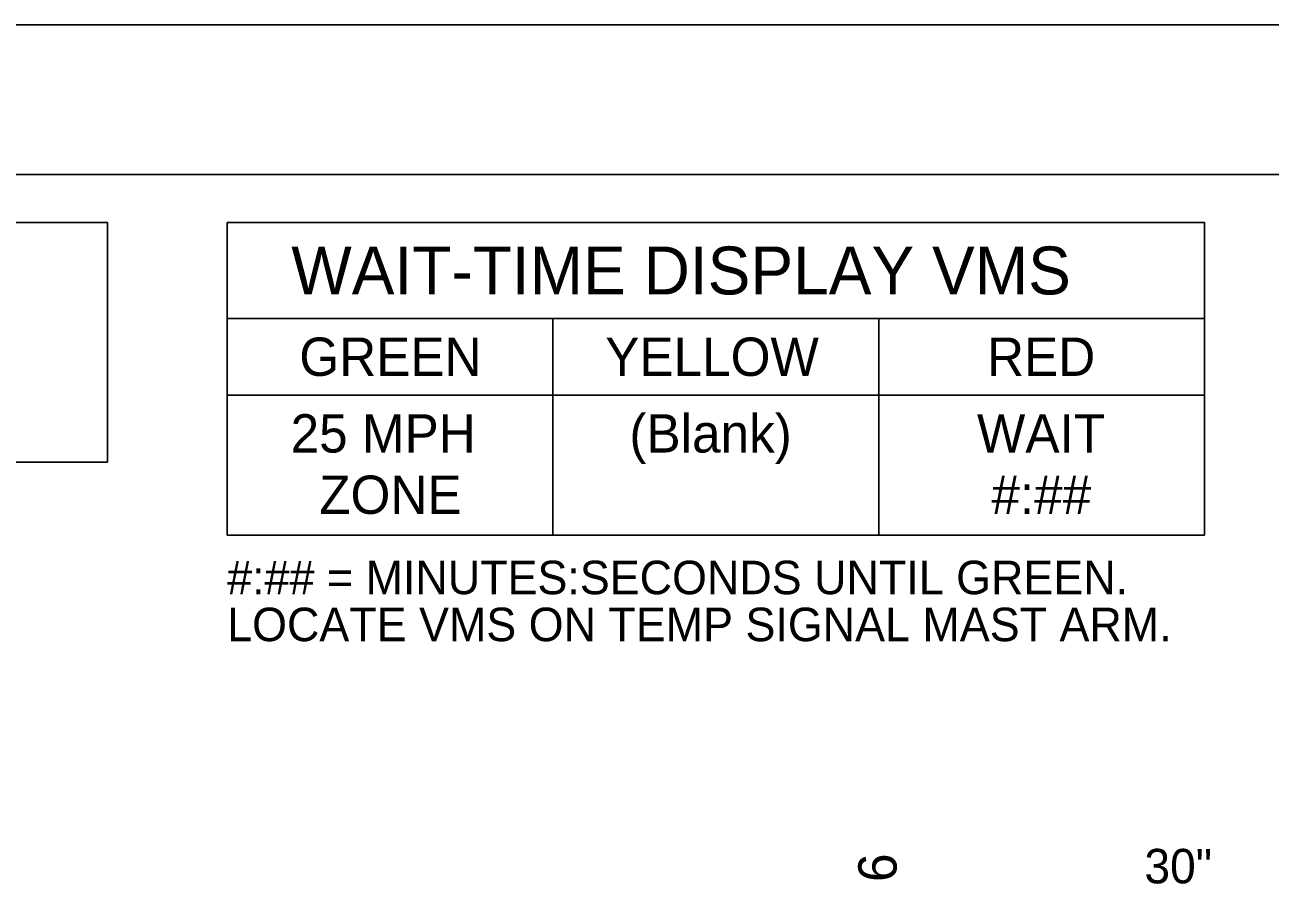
# Model space of a CAD drawing. Extents: x 99977 to 100176, y 99905 to 100011.
# Drawn here: x 100022.4 to 100024.999, y 99978.89 to 99980.687 of the extents above; entities that cross this region are included whole.
import ezdxf

# ---------------------------------------------------------------- set-up
doc = ezdxf.new("R2010")
doc.units = 0
for name, color, linetype in [('SH_GI_PlotLimits', 7, 'Continuous'), ('SH_GI_SheetBorder', 7, 'Continuous'), ('SH_TI_Tables', 7, 'Continuous'), ('TR_SN_ConstructionSigns', 7, 'Continuous'), ('TR_WZ_PortableChangeMessageSign', 7, 'Continuous'), ('TR_WZ_WorkZoneTextCurrent', 7, 'Continuous')]:
    doc.layers.add(name, color=color, linetype=linetype)

msp = doc.modelspace()

# ---------------------------------------------------------------- linework, layer by layer
at = {"layer": 'SH_GI_PlotLimits'}
msp.add_lwpolyline([(100019.0625, 99969.6875), (100036.0625, 99969.6875), (100036.0625, 99980.6875), (100019.0625, 99980.6875)], close=True, dxfattribs=at)
at = {"layer": 'SH_GI_SheetBorder'}
msp.add_line((100020, 99980.375), (100035.75, 99980.375), dxfattribs=at)
at = {"layer": 'SH_TI_Tables'}
msp.add_lwpolyline([(100020.1, 99980.275), (100022.5718, 99980.275), (100022.5718, 99979.775), (100020.1, 99979.775)], close=True, dxfattribs=at)
at = {"layer": 'TR_WZ_PortableChangeMessageSign'}
for p, q in [((100022.8218, 99980.275), (100024.8618, 99980.275)), ((100022.8218, 99979.6227), (100022.8218, 99980.275)), ((100024.8618, 99979.6227), (100024.8618, 99980.275)), ((100024.8618, 99980.075), (100022.8218, 99980.075)), ((100023.5018, 99979.6227), (100023.5018, 99980.075)), ((100024.1818, 99979.6227), (100024.1818, 99980.075)), ((100023.5018, 99979.915), (100022.8218, 99979.915)), ((100024.1818, 99979.915), (100023.5018, 99979.915)), ((100024.8618, 99979.915), (100024.1818, 99979.915)), ((100024.8618, 99979.6227), (100022.8218, 99979.6227))]:
    msp.add_line(p, q, dxfattribs=at)

# ---------------------------------------------------------------- texts
at = {"layer": 'TR_SN_ConstructionSigns'}
msp.add_text('30"', height=0.072, rotation=360, dxfattribs=at).set_placement((100024.7363, 99978.8959))
at = {"layer": 'TR_WZ_PortableChangeMessageSign'}
for s, height, p in [('WAIT-TIME DISPLAY VMS', 0.1, (100022.9556, 99980.125)), ('GREEN', 0.08, (100022.9724, 99979.955)), ('YELLOW', 0.08, (100023.6109, 99979.955)), ('RED', 0.08, (100024.4078, 99979.955)), ('25 MPH', 0.08, (100022.9542, 99979.795)), ('(Blank)', 0.08, (100023.6614, 99979.795)), ('WAIT', 0.08, (100024.3868, 99979.795)), ('ZONE', 0.08, (100023.0139, 99979.667)), ('#:##', 0.08, (100024.4169, 99979.667)), ('#:## = MINUTES:SECONDS UNTIL GREEN.', 0.07, (100022.8218, 99979.4993)), ('LOCATE VMS ON TEMP SIGNAL MAST ARM.', 0.07, (100022.8218, 99979.4013))]:
    msp.add_text(s, height=height, rotation=360, dxfattribs=at).set_placement(p)
at = {"layer": 'TR_WZ_WorkZoneTextCurrent'}
msp.add_text('6', height=0.08, rotation=90, dxfattribs=at).set_placement((100024.2191, 99978.8988))

doc.saveas('drawing.dxf')
